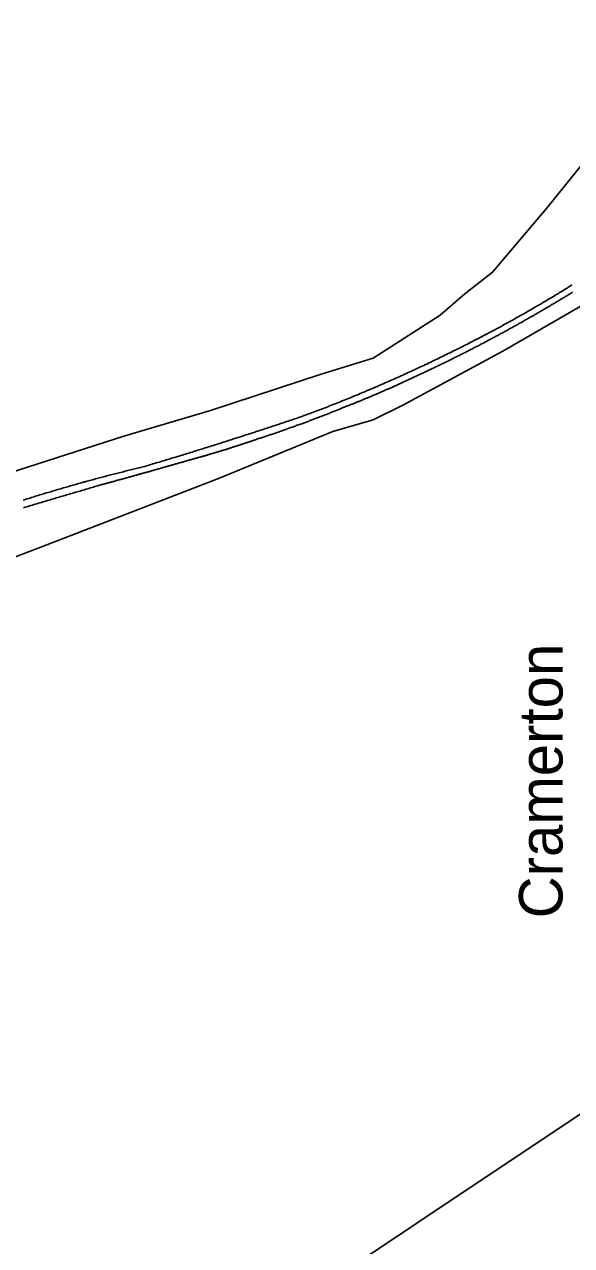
# Model space of a CAD drawing. Extents: x 1373043 to 1375788, y 550128 to 553055.
# Drawn here: x 1373360.4 to 1373392.9, y 550759.4 to 550832 of the extents above; entities that cross this region are included whole.
import ezdxf

# ---------------------------------------------------------------- set-up
doc = ezdxf.new("R2010")
doc.units = 0
for name, color, linetype in [('Old_Level_22', 7, 'Continuous'), ('Old_Level_32', 7, 'Continuous'), ('Old_Level_44', 7, 'Continuous'), ('Old_Level_48', 7, 'Continuous')]:
    doc.layers.add(name, color=color, linetype=linetype)

msp = doc.modelspace()

# ---------------------------------------------------------------- linework, layer by layer
at = {"layer": 'Old_Level_22'}
msp.add_line((1373389.809, 550778.885), (1373389.809, 550778.885), dxfattribs=at)
at = {"layer": 'Old_Level_32'}
for points in [[(1373312.503, 550789.888), (1373315.409, 550791.382), (1373319.747, 550792.767), (1373327.67, 550794.971), (1373334.41, 550797.08), (1373339.304, 550798.669), (1373343.713, 550800.126), (1373350.282, 550802.367), (1373366.35, 550807.53), (1373371.485, 550809.055), (1373378.054, 550811.225), (1373381.153, 550812.178), (1373385.117, 550814.728), (1373386.584, 550815.987), (1373388.24, 550817.281), (1373391.434, 550821.072), (1373396.236, 550827.007), (1373405.034, 550836.861), (1373410.471, 550842.938), (1373418.291, 550852.163), (1373421.651, 550856.004)], [(1373431.603, 550845.243), (1373413.092, 550828.113), (1373407.08, 550823.547), (1373401.46, 550820.021), (1373398.405, 550818.112), (1373388.839, 550812.593), (1373382.95, 550809.402), (1373381.154, 550808.504), (1373378.758, 550807.806), (1373371.971, 550805.013), (1373361.505, 550800.984), (1373351.424, 550797.143)]]:
    msp.add_lwpolyline(points, dxfattribs=at)
at = {"layer": 'Old_Level_44'}
for points in [[(1373387.459, 550813.38), (1373387.534, 550813.418), (1373387.611, 550813.457), (1373387.685, 550813.499), (1373387.763, 550813.541), (1373387.837, 550813.58), (1373387.912, 550813.619), (1373387.989, 550813.661), (1373388.063, 550813.699), (1373388.139, 550813.738), (1373388.215, 550813.78), (1373388.291, 550813.822), (1373388.365, 550813.861), (1373388.441, 550813.9), (1373388.517, 550813.942), (1373388.591, 550813.984), (1373388.666, 550814.022), (1373388.742, 550814.064), (1373388.816, 550814.103), (1373388.893, 550814.148), (1373388.968, 550814.187), (1373389.042, 550814.226), (1373389.118, 550814.271), (1373389.192, 550814.31), (1373389.266, 550814.352), (1373389.342, 550814.39), (1373389.417, 550814.436), (1373389.491, 550814.478), (1373389.567, 550814.516), (1373389.639, 550814.562), (1373389.714, 550814.6), (1373389.788, 550814.642), (1373389.864, 550814.688), (1373389.938, 550814.726), (1373390.012, 550814.768), (1373390.085, 550814.814), (1373390.161, 550814.856), (1373390.235, 550814.894), (1373390.308, 550814.94), (1373390.384, 550814.981), (1373390.458, 550815.027), (1373390.531, 550815.069), (1373390.605, 550815.111), (1373390.678, 550815.153), (1373390.754, 550815.195), (1373390.826, 550815.237), (1373390.901, 550815.282), (1373390.973, 550815.324), (1373391.049, 550815.369), (1373391.122, 550815.411), (1373391.196, 550815.456), (1373391.269, 550815.498), (1373391.341, 550815.54), (1373391.417, 550815.585), (1373391.49, 550815.631), (1373391.563, 550815.676), (1373391.637, 550815.718), (1373391.709, 550815.763), (1373391.782, 550815.805), (1373391.855, 550815.847), (1373391.929, 550815.895), (1373392.003, 550815.937), (1373392.076, 550815.983), (1373392.149, 550816.025), (1373392.221, 550816.073), (1373392.294, 550816.115), (1373392.367, 550816.16), (1373392.441, 550816.206), (1373392.514, 550816.251), (1373392.586, 550816.296), (1373392.659, 550816.341), (1373392.732, 550816.386), (1373392.804, 550816.432), (1373392.875, 550816.474), (1373392.948, 550816.522)], [(1373392.98, 550816.086), (1373392.925, 550816.054), (1373392.869, 550816.018), (1373392.814, 550815.986), (1373392.759, 550815.95), (1373392.704, 550815.918), (1373392.649, 550815.883), (1373392.594, 550815.853), (1373392.539, 550815.818), (1373392.481, 550815.786), (1373392.426, 550815.75), (1373392.372, 550815.718), (1373392.317, 550815.682), (1373392.262, 550815.65), (1373392.207, 550815.614), (1373392.149, 550815.585), (1373392.094, 550815.55), (1373392.039, 550815.518), (1373391.984, 550815.482), (1373391.929, 550815.45), (1373391.871, 550815.421), (1373391.816, 550815.385), (1373391.761, 550815.353), (1373391.705, 550815.317), (1373391.648, 550815.285), (1373391.593, 550815.253), (1373391.537, 550815.217), (1373391.482, 550815.188), (1373391.427, 550815.156), (1373391.369, 550815.12), (1373391.314, 550815.088), (1373391.259, 550815.056), (1373391.202, 550815.02), (1373391.148, 550814.991), (1373391.089, 550814.959), (1373391.035, 550814.927), (1373390.98, 550814.891), (1373390.923, 550814.859), (1373390.867, 550814.83), (1373390.81, 550814.797), (1373390.755, 550814.762), (1373390.699, 550814.73), (1373390.642, 550814.697), (1373390.586, 550814.668), (1373390.531, 550814.636), (1373390.474, 550814.6), (1373390.418, 550814.568), (1373390.361, 550814.536), (1373390.306, 550814.507), (1373390.25, 550814.474), (1373390.192, 550814.442), (1373390.137, 550814.41)], [(1373390.137, 550814.41), (1373390.074, 550814.371), (1373390.011, 550814.336), (1373389.948, 550814.3), (1373389.883, 550814.265), (1373389.82, 550814.229), (1373389.757, 550814.193), (1373389.694, 550814.158), (1373389.631, 550814.122), (1373389.567, 550814.087), (1373389.504, 550814.051), (1373389.441, 550814.016), (1373389.378, 550813.984), (1373389.312, 550813.948), (1373389.249, 550813.913), (1373389.186, 550813.877), (1373389.123, 550813.841), (1373389.058, 550813.806), (1373388.995, 550813.774), (1373388.93, 550813.738), (1373388.867, 550813.703), (1373388.804, 550813.667), (1373388.738, 550813.632), (1373388.675, 550813.596), (1373388.611, 550813.564), (1373388.548, 550813.528), (1373388.483, 550813.493), (1373388.42, 550813.457), (1373388.356, 550813.428), (1373388.293, 550813.393), (1373388.228, 550813.357), (1373388.163, 550813.322), (1373388.099, 550813.289), (1373388.036, 550813.254), (1373387.971, 550813.218), (1373387.907, 550813.186), (1373387.844, 550813.15), (1373387.779, 550813.121), (1373387.713, 550813.086), (1373387.65, 550813.05), (1373387.585, 550813.018), (1373387.521, 550812.982), (1373387.458, 550812.95), (1373387.393, 550812.915), (1373387.327, 550812.882), (1373387.262, 550812.847), (1373387.199, 550812.818), (1373387.135, 550812.782), (1373387.07, 550812.75), (1373387.004, 550812.714), (1373386.939, 550812.682), (1373386.875, 550812.647), (1373386.812, 550812.614), (1373386.747, 550812.585), (1373386.681, 550812.55), (1373386.616, 550812.517), (1373386.552, 550812.485), (1373386.487, 550812.45), (1373386.421, 550812.417), (1373386.357, 550812.388), (1373386.292, 550812.353), (1373386.227, 550812.32), (1373386.163, 550812.288), (1373386.097, 550812.259), (1373386.032, 550812.223), (1373385.967, 550812.191), (1373385.903, 550812.159), (1373385.837, 550812.127), (1373385.772, 550812.097), (1373385.707, 550812.062), (1373385.643, 550812.03), (1373385.575, 550811.997), (1373385.51, 550811.965), (1373385.446, 550811.936), (1373385.381, 550811.904), (1373385.315, 550811.871), (1373385.249, 550811.839), (1373385.184, 550811.81), (1373385.118, 550811.778), (1373385.053, 550811.745), (1373384.987, 550811.713), (1373384.921, 550811.684), (1373384.856, 550811.652), (1373384.792, 550811.62), (1373384.726, 550811.587), (1373384.659, 550811.555), (1373384.595, 550811.526), (1373384.529, 550811.494), (1373384.462, 550811.461), (1373384.396, 550811.429), (1373384.332, 550811.403), (1373384.265, 550811.371), (1373384.199, 550811.339), (1373384.135, 550811.309), (1373384.067, 550811.277), (1373384.002, 550811.248), (1373383.936, 550811.219), (1373383.87, 550811.187), (1373383.803, 550811.154), (1373383.739, 550811.129)], [(1373377.059, 550808.758), (1373377.165, 550808.797), (1373377.273, 550808.839), (1373377.382, 550808.878), (1373377.488, 550808.92), (1373377.596, 550808.962), (1373377.704, 550809), (1373377.811, 550809.039), (1373377.919, 550809.084), (1373378.026, 550809.123), (1373378.134, 550809.165), (1373378.239, 550809.21), (1373378.349, 550809.249), (1373378.454, 550809.291), (1373378.562, 550809.333), (1373378.668, 550809.375), (1373378.775, 550809.417), (1373378.883, 550809.462), (1373378.99, 550809.501), (1373379.096, 550809.543), (1373379.205, 550809.588), (1373379.311, 550809.63), (1373379.418, 550809.675), (1373379.523, 550809.717), (1373379.629, 550809.763), (1373379.736, 550809.804), (1373379.842, 550809.846), (1373379.949, 550809.892), (1373380.057, 550809.934), (1373380.164, 550809.979), (1373380.269, 550810.024), (1373380.374, 550810.069), (1373380.48, 550810.111), (1373380.587, 550810.153), (1373380.693, 550810.202), (1373380.798, 550810.244), (1373380.905, 550810.289), (1373381.012, 550810.337), (1373381.117, 550810.379), (1373381.223, 550810.428), (1373381.328, 550810.47), (1373381.433, 550810.518), (1373381.54, 550810.56), (1373381.646, 550810.609), (1373381.75, 550810.654), (1373381.856, 550810.699), (1373381.961, 550810.744), (1373382.068, 550810.793), (1373382.171, 550810.841), (1373382.278, 550810.886), (1373382.383, 550810.932), (1373382.486, 550810.977), (1373382.592, 550811.025), (1373382.697, 550811.074), (1373382.801, 550811.119), (1373382.907, 550811.167), (1373383.012, 550811.213), (1373383.116, 550811.261), (1373383.221, 550811.313), (1373383.326, 550811.361), (1373383.429, 550811.406), (1373383.534, 550811.455), (1373383.639, 550811.5), (1373383.742, 550811.552), (1373383.847, 550811.6), (1373383.95, 550811.649), (1373384.055, 550811.697), (1373384.16, 550811.745), (1373384.264, 550811.797), (1373384.369, 550811.842), (1373384.472, 550811.894), (1373384.575, 550811.942), (1373384.68, 550811.994), (1373384.784, 550812.046), (1373384.889, 550812.091), (1373384.99, 550812.143), (1373385.095, 550812.194), (1373385.197, 550812.243), (1373385.302, 550812.291), (1373385.404, 550812.343), (1373385.509, 550812.395), (1373385.61, 550812.446), (1373385.715, 550812.498), (1373385.817, 550812.55), (1373385.921, 550812.601), (1373386.024, 550812.65), (1373386.127, 550812.701), (1373386.229, 550812.753), (1373386.331, 550812.805), (1373386.436, 550812.856), (1373386.537, 550812.908), (1373386.641, 550812.96), (1373386.742, 550813.015), (1373386.846, 550813.063), (1373386.948, 550813.115), (1373387.049, 550813.17), (1373387.153, 550813.221), (1373387.254, 550813.273), (1373387.358, 550813.328), (1373387.459, 550813.38)], [(1373383.739, 550811.129), (1373383.695, 550811.103), (1373383.653, 550811.083), (1373383.61, 550811.064), (1373383.569, 550811.045), (1373383.526, 550811.025), (1373383.484, 550811.006), (1373383.442, 550810.987), (1373383.4, 550810.967), (1373383.356, 550810.948), (1373383.316, 550810.925), (1373383.272, 550810.906), (1373383.23, 550810.886), (1373383.187, 550810.864), (1373383.145, 550810.844), (1373383.103, 550810.825), (1373383.059, 550810.806), (1373383.017, 550810.786), (1373382.975, 550810.764), (1373382.932, 550810.744), (1373382.89, 550810.725), (1373382.846, 550810.706), (1373382.804, 550810.686), (1373382.762, 550810.67), (1373382.718, 550810.651), (1373382.675, 550810.631), (1373382.634, 550810.612), (1373382.591, 550810.593), (1373382.547, 550810.573), (1373382.507, 550810.554), (1373382.463, 550810.531), (1373382.42, 550810.512), (1373382.378, 550810.492), (1373382.334, 550810.473), (1373382.292, 550810.457), (1373382.248, 550810.437), (1373382.207, 550810.418), (1373382.163, 550810.399), (1373382.121, 550810.379), (1373382.077, 550810.36), (1373382.035, 550810.344), (1373381.992, 550810.324), (1373381.948, 550810.305), (1373381.906, 550810.286), (1373381.864, 550810.266), (1373381.821, 550810.25), (1373381.777, 550810.231), (1373381.735, 550810.211), (1373381.691, 550810.189), (1373381.648, 550810.176), (1373381.606, 550810.153), (1373381.564, 550810.134), (1373381.52, 550810.115), (1373381.477, 550810.098), (1373381.433, 550810.079), (1373381.389, 550810.06), (1373381.346, 550810.043), (1373381.304, 550810.024), (1373381.262, 550810.005), (1373381.218, 550809.989), (1373381.175, 550809.969), (1373381.131, 550809.95), (1373381.089, 550809.934), (1373381.045, 550809.914), (1373381.002, 550809.895), (1373380.958, 550809.879), (1373380.915, 550809.859), (1373380.873, 550809.84), (1373380.829, 550809.824), (1373380.785, 550809.804), (1373380.742, 550809.788), (1373380.698, 550809.769), (1373380.655, 550809.753), (1373380.613, 550809.733), (1373380.569, 550809.717), (1373380.525, 550809.698), (1373380.482, 550809.679), (1373380.438, 550809.662), (1373380.396, 550809.643), (1373380.353, 550809.627), (1373380.309, 550809.607), (1373380.266, 550809.591), (1373380.222, 550809.572), (1373380.178, 550809.556), (1373380.136, 550809.54), (1373380.093, 550809.52), (1373380.049, 550809.504), (1373380.006, 550809.485), (1373379.96, 550809.469), (1373379.917, 550809.449), (1373379.873, 550809.433), (1373379.831, 550809.417), (1373379.788, 550809.398), (1373379.744, 550809.381), (1373379.7, 550809.362), (1373379.657, 550809.349), (1373379.612, 550809.333), (1373379.568, 550809.314), (1373379.526, 550809.297), (1373379.482, 550809.281)], [(1373379.482, 550809.281), (1373379.429, 550809.255), (1373379.376, 550809.236), (1373379.322, 550809.213), (1373379.269, 550809.194), (1373379.216, 550809.172), (1373379.163, 550809.152), (1373379.109, 550809.126), (1373379.054, 550809.107), (1373379.001, 550809.084), (1373378.948, 550809.065), (1373378.895, 550809.039), (1373378.843, 550809.02), (1373378.79, 550809), (1373378.736, 550808.978), (1373378.683, 550808.958), (1373378.63, 550808.936), (1373378.575, 550808.913), (1373378.522, 550808.894), (1373378.468, 550808.871), (1373378.415, 550808.852), (1373378.362, 550808.832), (1373378.307, 550808.807), (1373378.254, 550808.787), (1373378.2, 550808.768), (1373378.147, 550808.745), (1373378.094, 550808.726), (1373378.039, 550808.706), (1373377.985, 550808.687), (1373377.932, 550808.661), (1373377.879, 550808.642), (1373377.824, 550808.622), (1373377.771, 550808.603), (1373377.717, 550808.584), (1373377.664, 550808.561), (1373377.609, 550808.542), (1373377.556, 550808.519), (1373377.504, 550808.5), (1373377.448, 550808.48), (1373377.394, 550808.461), (1373377.343, 550808.438), (1373377.286, 550808.419), (1373377.233, 550808.4), (1373377.181, 550808.38), (1373377.125, 550808.358), (1373377.073, 550808.338), (1373377.02, 550808.319), (1373376.963, 550808.3), (1373376.912, 550808.28), (1373376.855, 550808.261), (1373376.802, 550808.241), (1373376.747, 550808.222), (1373376.694, 550808.203), (1373376.64, 550808.183), (1373376.585, 550808.164), (1373376.532, 550808.141), (1373376.477, 550808.122), (1373376.424, 550808.103), (1373376.369, 550808.083), (1373376.316, 550808.064), (1373376.261, 550808.044), (1373376.208, 550808.025), (1373376.153, 550808.006), (1373376.099, 550807.986), (1373376.044, 550807.967), (1373375.991, 550807.944), (1373375.936, 550807.931), (1373375.883, 550807.912), (1373375.828, 550807.889), (1373375.775, 550807.87), (1373375.72, 550807.851), (1373375.667, 550807.831), (1373375.612, 550807.815), (1373375.557, 550807.796), (1373375.503, 550807.776), (1373375.449, 550807.757), (1373375.395, 550807.741), (1373375.34, 550807.721), (1373375.284, 550807.702), (1373375.232, 550807.683), (1373375.176, 550807.667), (1373375.121, 550807.647), (1373375.068, 550807.628), (1373375.013, 550807.612), (1373374.958, 550807.592), (1373374.904, 550807.573), (1373374.85, 550807.557), (1373374.795, 550807.537), (1373374.741, 550807.518), (1373374.686, 550807.502), (1373374.632, 550807.482), (1373374.578, 550807.466), (1373374.523, 550807.447), (1373374.467, 550807.428), (1373374.412, 550807.411), (1373374.359, 550807.392), (1373374.304, 550807.376), (1373374.249, 550807.356), (1373374.194, 550807.34), (1373374.141, 550807.321)], [(1373367.488, 550805.713), (1373367.585, 550805.742), (1373367.683, 550805.771), (1373367.78, 550805.8), (1373367.877, 550805.832), (1373367.975, 550805.858), (1373368.071, 550805.887), (1373368.168, 550805.919), (1373368.266, 550805.945), (1373368.363, 550805.977), (1373368.458, 550806.003), (1373368.557, 550806.032), (1373368.654, 550806.065), (1373368.75, 550806.09), (1373368.849, 550806.123), (1373368.946, 550806.152), (1373369.041, 550806.181), (1373369.14, 550806.21), (1373369.237, 550806.242), (1373369.333, 550806.268), (1373369.43, 550806.3), (1373369.529, 550806.326), (1373369.624, 550806.359), (1373369.721, 550806.388), (1373369.819, 550806.417), (1373369.916, 550806.446), (1373370.012, 550806.478), (1373370.109, 550806.507), (1373370.205, 550806.536), (1373370.304, 550806.568), (1373370.401, 550806.594), (1373370.496, 550806.627), (1373370.593, 550806.659), (1373370.691, 550806.685), (1373370.788, 550806.717), (1373370.885, 550806.749), (1373370.981, 550806.775), (1373371.077, 550806.807), (1373371.176, 550806.84), (1373371.273, 550806.866), (1373371.368, 550806.898), (1373371.465, 550806.93), (1373371.562, 550806.962), (1373371.659, 550806.988), (1373371.754, 550807.021), (1373371.852, 550807.053), (1373371.949, 550807.082), (1373372.046, 550807.111), (1373372.143, 550807.143), (1373372.238, 550807.176), (1373372.335, 550807.205), (1373372.432, 550807.237), (1373372.529, 550807.269), (1373372.624, 550807.295), (1373372.721, 550807.327), (1373372.82, 550807.36), (1373372.917, 550807.392), (1373373.014, 550807.421), (1373373.109, 550807.453), (1373373.206, 550807.486), (1373373.303, 550807.511), (1373373.398, 550807.544), (1373373.495, 550807.576), (1373373.592, 550807.608), (1373373.689, 550807.637), (1373373.784, 550807.67), (1373373.881, 550807.702), (1373373.978, 550807.734), (1373374.074, 550807.763), (1373374.17, 550807.796), (1373374.267, 550807.828), (1373374.363, 550807.86), (1373374.46, 550807.889), (1373374.556, 550807.922), (1373374.653, 550807.954), (1373374.749, 550807.986), (1373374.846, 550808.015), (1373374.942, 550808.048), (1373375.037, 550808.08), (1373375.134, 550808.115), (1373375.229, 550808.148), (1373375.326, 550808.177), (1373375.423, 550808.209), (1373375.52, 550808.241), (1373375.615, 550808.274), (1373375.712, 550808.303), (1373375.809, 550808.335), (1373375.906, 550808.371), (1373375.999, 550808.403), (1373376.096, 550808.435), (1373376.193, 550808.464), (1373376.288, 550808.497), (1373376.385, 550808.532), (1373376.482, 550808.564), (1373376.576, 550808.597), (1373376.673, 550808.626), (1373376.77, 550808.658), (1373376.865, 550808.694), (1373376.962, 550808.726), (1373377.059, 550808.758)], [(1373374.141, 550807.321), (1373374.1, 550807.308), (1373374.06, 550807.292), (1373374.02, 550807.279), (1373373.978, 550807.266), (1373373.939, 550807.253), (1373373.897, 550807.237), (1373373.858, 550807.224), (1373373.816, 550807.208), (1373373.777, 550807.198), (1373373.735, 550807.182), (1373373.693, 550807.169), (1373373.655, 550807.153), (1373373.613, 550807.143), (1373373.574, 550807.13), (1373373.532, 550807.114), (1373373.491, 550807.105), (1373373.451, 550807.088), (1373373.411, 550807.075), (1373373.37, 550807.063), (1373373.33, 550807.05), (1373373.288, 550807.037), (1373373.249, 550807.021), (1373373.207, 550807.008), (1373373.167, 550806.998), (1373373.127, 550806.982), (1373373.086, 550806.969), (1373373.044, 550806.956), (1373373.005, 550806.943), (1373372.963, 550806.93), (1373372.921, 550806.917), (1373372.883, 550806.901), (1373372.841, 550806.891), (1373372.8, 550806.878), (1373372.76, 550806.862), (1373372.72, 550806.853), (1373372.678, 550806.84), (1373372.639, 550806.827), (1373372.597, 550806.811), (1373372.557, 550806.801), (1373372.515, 550806.788), (1373372.476, 550806.775), (1373372.434, 550806.762), (1373372.392, 550806.749), (1373372.353, 550806.736), (1373372.311, 550806.727), (1373372.271, 550806.714), (1373372.229, 550806.698), (1373372.19, 550806.685), (1373372.148, 550806.675), (1373372.108, 550806.662), (1373372.066, 550806.649), (1373372.027, 550806.633), (1373371.985, 550806.623), (1373371.943, 550806.61), (1373371.903, 550806.601), (1373371.861, 550806.588), (1373371.822, 550806.575), (1373371.78, 550806.565), (1373371.739, 550806.549), (1373371.697, 550806.536), (1373371.659, 550806.523), (1373371.617, 550806.514), (1373371.575, 550806.501), (1373371.534, 550806.488), (1373371.492, 550806.478), (1373371.452, 550806.465), (1373371.412, 550806.452), (1373371.371, 550806.443), (1373371.329, 550806.43), (1373371.287, 550806.417), (1373371.247, 550806.404), (1373371.205, 550806.391), (1373371.166, 550806.378), (1373371.124, 550806.368), (1373371.084, 550806.355), (1373371.042, 550806.342), (1373371, 550806.333), (1373370.959, 550806.32), (1373370.918, 550806.307), (1373370.879, 550806.297), (1373370.837, 550806.284), (1373370.796, 550806.278), (1373370.754, 550806.265), (1373370.712, 550806.252), (1373370.672, 550806.242), (1373370.63, 550806.229), (1373370.59, 550806.216), (1373370.548, 550806.207), (1373370.506, 550806.194), (1373370.467, 550806.181), (1373370.425, 550806.171), (1373370.385, 550806.158), (1373370.343, 550806.145), (1373370.302, 550806.136), (1373370.26, 550806.126), (1373370.218, 550806.116), (1373370.178, 550806.103), (1373370.136, 550806.09), (1373370.096, 550806.081)], [(1373370.096, 550806.081), (1373370.044, 550806.065), (1373369.992, 550806.052), (1373369.942, 550806.036), (1373369.889, 550806.019), (1373369.837, 550806.003), (1373369.786, 550805.99), (1373369.736, 550805.977), (1373369.684, 550805.961), (1373369.631, 550805.945), (1373369.579, 550805.929), (1373369.529, 550805.919), (1373369.477, 550805.903), (1373369.425, 550805.887), (1373369.372, 550805.871), (1373369.322, 550805.858), (1373369.27, 550805.842), (1373369.219, 550805.829), (1373369.165, 550805.813), (1373369.114, 550805.8), (1373369.064, 550805.784), (1373369.012, 550805.768), (1373368.96, 550805.751), (1373368.907, 550805.742), (1373368.857, 550805.726), (1373368.805, 550805.709), (1373368.754, 550805.693), (1373368.704, 550805.68), (1373368.65, 550805.667), (1373368.599, 550805.651), (1373368.547, 550805.635), (1373368.497, 550805.622), (1373368.444, 550805.606), (1373368.392, 550805.59), (1373368.34, 550805.577), (1373368.29, 550805.564), (1373368.237, 550805.548), (1373368.185, 550805.532), (1373368.134, 550805.519), (1373368.084, 550805.506), (1373368.032, 550805.49), (1373367.979, 550805.474), (1373367.927, 550805.461), (1373367.877, 550805.445), (1373367.825, 550805.428), (1373367.772, 550805.419), (1373367.72, 550805.403), (1373367.67, 550805.386), (1373367.619, 550805.374), (1373367.565, 550805.357), (1373367.514, 550805.344), (1373367.464, 550805.332), (1373367.412, 550805.315), (1373367.359, 550805.299), (1373367.307, 550805.283), (1373367.257, 550805.273), (1373367.205, 550805.257), (1373367.152, 550805.241), (1373367.1, 550805.228), (1373367.05, 550805.212), (1373366.998, 550805.196), (1373366.945, 550805.186), (1373366.893, 550805.17), (1373366.843, 550805.154), (1373366.79, 550805.141), (1373366.738, 550805.128), (1373366.687, 550805.112), (1373366.637, 550805.099), (1373366.583, 550805.083), (1373366.532, 550805.07), (1373366.48, 550805.057), (1373366.428, 550805.041), (1373366.377, 550805.028), (1373366.325, 550805.012), (1373366.273, 550804.996), (1373366.22, 550804.986), (1373366.17, 550804.97), (1373366.118, 550804.954), (1373366.067, 550804.941), (1373366.013, 550804.925), (1373365.963, 550804.915), (1373365.912, 550804.899), (1373365.86, 550804.883), (1373365.807, 550804.87), (1373365.757, 550804.854), (1373365.705, 550804.841), (1373365.652, 550804.828), (1373365.6, 550804.812), (1373365.55, 550804.799), (1373365.497, 550804.783), (1373365.445, 550804.77), (1373365.393, 550804.757), (1373365.342, 550804.741), (1373365.29, 550804.728), (1373365.238, 550804.715), (1373365.187, 550804.699), (1373365.133, 550804.686), (1373365.083, 550804.669), (1373365.032, 550804.657), (1373364.978, 550804.644)], [(1373360.363, 550803.733), (1373360.444, 550803.759), (1373360.526, 550803.788), (1373360.61, 550803.81), (1373360.691, 550803.839), (1373360.773, 550803.862), (1373360.856, 550803.891), (1373360.937, 550803.914), (1373361.019, 550803.943), (1373361.101, 550803.965), (1373361.182, 550803.991), (1373361.266, 550804.017), (1373361.348, 550804.043), (1373361.431, 550804.069), (1373361.511, 550804.091), (1373361.594, 550804.117), (1373361.676, 550804.143), (1373361.76, 550804.169), (1373361.842, 550804.195), (1373361.923, 550804.217), (1373362.006, 550804.24), (1373362.088, 550804.269), (1373362.17, 550804.292), (1373362.254, 550804.314), (1373362.337, 550804.34), (1373362.419, 550804.366), (1373362.501, 550804.392), (1373362.584, 550804.414), (1373362.664, 550804.437), (1373362.748, 550804.46), (1373362.831, 550804.485), (1373362.913, 550804.508), (1373362.995, 550804.531), (1373363.078, 550804.556), (1373363.162, 550804.579), (1373363.244, 550804.602), (1373363.326, 550804.628), (1373363.409, 550804.65), (1373363.491, 550804.673), (1373363.575, 550804.699), (1373363.657, 550804.721), (1373363.741, 550804.744), (1373363.824, 550804.77), (1373363.908, 550804.792), (1373363.99, 550804.815), (1373364.072, 550804.834), (1373364.155, 550804.86), (1373364.239, 550804.883), (1373364.321, 550804.905), (1373364.403, 550804.931), (1373364.487, 550804.95), (1373364.571, 550804.973), (1373364.654, 550804.996), (1373364.736, 550805.015), (1373364.818, 550805.041), (1373364.904, 550805.063), (1373364.986, 550805.083), (1373365.069, 550805.105), (1373365.151, 550805.128), (1373365.233, 550805.151), (1373365.319, 550805.173), (1373365.401, 550805.193), (1373365.484, 550805.219), (1373365.569, 550805.238), (1373365.652, 550805.257), (1373365.734, 550805.28), (1373365.816, 550805.299), (1373365.902, 550805.322), (1373365.984, 550805.344), (1373366.067, 550805.367), (1373366.152, 550805.386), (1373366.235, 550805.406), (1373366.319, 550805.428), (1373366.401, 550805.451), (1373366.485, 550805.47), (1373366.569, 550805.49), (1373366.651, 550805.512), (1373366.737, 550805.532), (1373366.819, 550805.551), (1373366.902, 550805.571), (1373366.987, 550805.59), (1373367.069, 550805.616), (1373367.153, 550805.635), (1373367.236, 550805.655), (1373367.321, 550805.674), (1373367.404, 550805.693), (1373367.488, 550805.713)], [(1373364.978, 550804.644), (1373364.891, 550804.618), (1373364.802, 550804.592), (1373364.715, 550804.563), (1373364.626, 550804.54), (1373364.538, 550804.511), (1373364.449, 550804.489), (1373364.362, 550804.46), (1373364.273, 550804.437), (1373364.185, 550804.411), (1373364.097, 550804.385), (1373364.008, 550804.359), (1373363.919, 550804.33), (1373363.832, 550804.308), (1373363.745, 550804.279), (1373363.656, 550804.256), (1373363.567, 550804.23), (1373363.478, 550804.204), (1373363.389, 550804.179), (1373363.302, 550804.15), (1373363.215, 550804.127), (1373363.126, 550804.098), (1373363.037, 550804.075), (1373362.949, 550804.046), (1373362.861, 550804.02), (1373362.773, 550803.998), (1373362.685, 550803.969), (1373362.597, 550803.946), (1373362.508, 550803.917), (1373362.421, 550803.891), (1373362.332, 550803.865), (1373362.243, 550803.839), (1373362.156, 550803.81), (1373362.067, 550803.788), (1373361.98, 550803.759), (1373361.891, 550803.736), (1373361.802, 550803.71), (1373361.715, 550803.681), (1373361.626, 550803.659), (1373361.539, 550803.63), (1373361.45, 550803.604), (1373361.361, 550803.578), (1373361.272, 550803.552), (1373361.185, 550803.523), (1373361.098, 550803.5), (1373361.009, 550803.471), (1373360.92, 550803.445), (1373360.832, 550803.423), (1373360.746, 550803.394), (1373360.657, 550803.368), (1373360.568, 550803.342), (1373360.48, 550803.316), (1373360.392, 550803.287)]]:
    msp.add_lwpolyline(points, dxfattribs=at)
at = {"layer": 'Old_Level_48'}
msp.add_lwpolyline([(1373417.885, 550755.2), (1373405.508, 550775.31), (1373351.12, 550739.005)], dxfattribs=at)

# ---------------------------------------------------------------- texts
at = {"layer": 'Old_Level_22'}
msp.add_text('Cramerton ', height=2.5837, rotation=90, dxfattribs=at).set_placement((1373392.393, 550778.885))

doc.saveas('drawing.dxf')
